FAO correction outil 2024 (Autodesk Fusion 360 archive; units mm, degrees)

design "FAO correction outil" references "brut correction outil", "Correction outil"
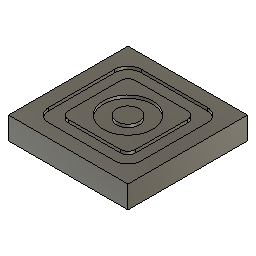
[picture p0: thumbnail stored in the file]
component_insert "Insertion d'un composant1"
component_insert "Insertion d'un composant2"
work_plane "Plan de construction" AlongDistance 0
sketch "Esquisse1" plane through (0, 0, 15) normal (0, 0, 1) x axis (1, 0, 0)
  line L1 (31, -22) -> (31, 22)
  line L2 (28.4, 4.5033) -> (25.5072, 1.0928)
  line L3 (28.4, -4.5033) -> (25.5072, -1.0928)
  line L4 (15.2762, -12.0803) -> (45.0436, 5.1058)
  line L5 (28.4, -4.5033) -> (26.4, -1.0392)
  arc A1 centre (25.8, 0) radius 5.2 clockwise from (28.4, 4.5033) to (28.4, -4.5033)
  circle C1 centre (25.5072, -1.0928) radius 4
  circle C2 centre (26.4, -1.0392) radius 4
  point P4 (31, 0)
  point P8 (25.5072, 1.0928)
  point P9 (25.5072, 1.0928)
  point P7 (28.4, 4.5033)
  point P10 (28.4, 4.5033)
  point P2 (25.5072, -1.0928)
  point P11 (25.5072, -1.0928)
  point P3 (28.4, -4.5033)
  point P12 (28.4, -4.5033)
  point P14 (25.5072, -1.0928)
  point P15 (26.4, -1.0392)
  point P18 (26.4, -1.0392)
  point P1 (0, 0)
  midpoint P4 L1
  coincident P8 P9
  coincident P7 P10
  coincident P2 P11
  coincident P3 P12
  coincident P4 A1
  tangent L1 A1
  coincident P2 P14
  tangent A1 C2
  coincident P12 C2
  tangent A1 L4
  coincident P12 L4
  coincident P15 P18
  dimension "d2" distance P1 P2 = 25.5072 (= "d3")
  dimension "d3" distance P1 P8 = 25.5072
  dimension "d4" distance P1 P2 = 1.0928
  dimension "d5" distance P1 P8 = 1.0928 (= "d4")
  dimension "d6" distance P1 P3 = 28.4
  dimension "d7" distance P1 P7 = 28.4 (= "d6")
  dimension "d8" distance P1 P7 = 4.5033
  dimension "d9" distance P1 P3 = 4.5033 (= "d8")
  dimension "d10" diameter C1 = 8
  dimension "d11" diameter C2 = 8
sketch "Esquisse2" plane through (0, 0, 15) normal (0, 0, 1) x axis (1, 0, 0)
  line L1 (31, -22) -> (31, 22)
  line L2 (28.6, 4.1569) -> (25.9072, 1.0928)
  line L3 (28.6, -4.1569) -> (25.9072, -1.0928)
  line L4 (33.5853, -1.2661) -> (26.6459, -5.29)
  line L5 (23.8353, 4.06) -> (28.6, -4.1569)
  arc A1 centre (26.2, 0) radius 4.8 clockwise from (28.6, 4.1569) to (28.6, -4.1569)
  circle C1 centre (26.5935, -0.6966) radius 4
  circle C2 centre (25.9072, -1.0928) radius 4
  circle C3 centre (26.3427, -0.264) radius 4
  point P2 (25.9072, 1.0928)
  point P3 (25.9072, -1.0928)
  point P4 (28.6, -4.1569)
  point P5 (28.6, 4.1569)
  point P6 (31, 0)
  point P10 (25.9072, 1.0928)
  point P11 (28.6, 4.1569)
  point P12 (25.9072, -1.0928)
  point P13 (28.6, -4.1569)
  point P14 (26.5935, -0.6966)
  point P18 (25.9072, -1.0928)
  point P19 (26.3427, -0.264)
  point P20 (26.3427, -0.264)
  point P1 (0, 0)
  vertical P2 P3
  vertical P4 P5
  midpoint P6 L1
  coincident P6 A1
  tangent L1 A1
  coincident P2 P10
  coincident P5 P11
  coincident P3 P12
  coincident P4 P13
  tangent A1 C1
  coincident P13 L4
  tangent A1 L4
  perpendicular L4 L5
  coincident P14 L5
  coincident P12 P18
  coincident L5 P19
  coincident P19 P20
  dimension "d12" distance P1 P2 = 25.9072
  dimension "d13" distance P1 P2 = 1.0928
  dimension "d14" distance P1 P3 = 1.0928 (= "d13")
  dimension "d15" distance P1 P5 = 28.6
  dimension "d16" distance P1 P5 = 4.1569
  dimension "d17" distance P1 P4 = 4.1569 (= "d16")
  dimension "d18" diameter C1 = 8
  dimension "d20" diameter C2 = 8
  dimension "d21" distance P14 P19 = 0.5
  dimension "d22" diameter C3 = 8
sketch "Esquisse3" plane through (0, 0, 15) normal (0, 0, 1) x axis (1, 0, 0)
  line L1 (31, -22) -> (31, 22)
  line L2 (30.5778, 2.3941) -> (26.5455, 1.7778)
  line L3 (30.5778, -2.3941) -> (26.5455, -1.7778)
  line L4 (33.1739, -4.7381) -> (28.8901, 7.0308)
  line L5 (25.6476, 0.5996) -> (32.956, 3.2598)
  arc A1 centre (24.0008, 0) radius 6.9992 clockwise from (30.5778, 2.3941) to (30.5778, -2.3941)
  circle C1 centre (26.5455, 1.7778) radius 4
  circle C2 centre (26.8191, 1.026) radius 4
  circle C3 centre (26.4432, 0.8892) radius 4
  point P3 (30.5778, 2.3941)
  point P4 (30.5778, -2.3941)
  point P2 (26.5455, 1.7778)
  point P9 (26.5455, 1.7778)
  point P10 (30.5778, 2.3941)
  point P5 (26.5455, -1.7778)
  point P11 (26.5455, -1.7778)
  point P12 (30.5778, -2.3941)
  point P13 (26.5455, 1.7778)
  point P18 (26.8191, 1.026)
  point P19 (26.4432, 0.8892)
  point P20 (26.4432, 0.8892)
  point P21 (26.0675, 0.7524)
  point P1 (0, 0)
  vertical P3 P4
  tangent L1 A1
  coincident P2 P9
  coincident P3 P10
  coincident P5 P11
  coincident P4 P12
  coincident P2 P13
  tangent A1 L4
  coincident P10 L4
  perpendicular L4 L5
  coincident P10 L5
  coincident L5 P18
  coincident P3 C2
  coincident L5 P19
  coincident P19 P20
  coincident L5 P21
  dimension "d23" distance P1 P2 = 26.5455
  dimension "d24" distance P1 P5 = 26.5455 (= "d23")
  dimension "d25" distance P1 P3 = 30.5778
  dimension "d26" distance P1 P3 = 2.3941
  dimension "d27" distance P1 P4 = 2.3941 (= "d26")
  dimension "d28" distance P1 P2 = 1.7778
  dimension "d29" distance P1 P5 = 1.7778 (= "d28")
  dimension "d30" diameter C1 = 8
  dimension "d31" diameter C2 = 8
  dimension "d32" distance P18 P19 = 0.4
  dimension "d33" diameter C3 = 8
  dimension "d34" distance P1 P21 = 0.7524
  dimension "d35" distance P1 P21 = 26.0675

design "brut correction outil"
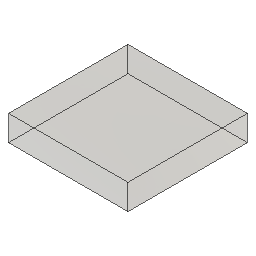
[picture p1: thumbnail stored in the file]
sketch "Esquisse" plane through (0, 0, 0) normal (0, 0, 1) x axis (1, 0, 0)
  line L1 (40, 40) -> (-40, 40)
  line L2 (40, -40) -> (40, 40)
  line L3 (-40, -40) -> (40, -40)
  line L4 (-40, 40) -> (-40, -40)
  line L5 (40, -40) -> (-40, 40)
  line L6 (-40, -40) -> (40, 40)
  point P6 (0, 0)
  point P1 (0, 0)
  point P4 (40, -40)
  point P5 (-40, -40)
  point P3 (40, 40)
  horizontal L1
  perpendicular L1 L2
  parallel L1 L3
  parallel L2 L4
  coincident L5 P6
  coincident L6 P6
  coincident P1 P6
  dimension "d1" distance P4 P5 = 80
  dimension "d2" distance P3 P4 = 80
extrude "Extrusion" new body sketch "Esquisse" profile of L1 L2 L3 L4 along normal blind 17

design "Correction outil"
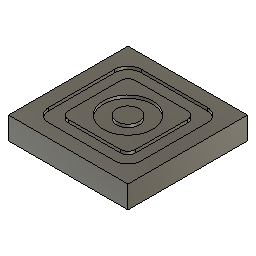
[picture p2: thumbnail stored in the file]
sketch "Esquisse1" plane through (0, 0, 0) normal (0, 0, 1) x axis (1, 0, 0)
  line L1 (-40, 40) -> (40, 40)
  line L2 (-40, -40) -> (-40, 40)
  line L3 (40, -40) -> (-40, -40)
  line L4 (40, 40) -> (40, -40)
  line L5 (-40, -40) -> (40, 40)
  line L6 (40, -40) -> (-40, 40)
  point P6 (0, 0)
  point P1 (0, 0)
  point P4 (-40, -40)
  point P5 (40, -40)
  point P3 (-40, 40)
  horizontal L1
  perpendicular L1 L2
  parallel L1 L3
  parallel L2 L4
  coincident L5 P6
  coincident L6 P6
  coincident P1 P6
  dimension "d1" distance P4 P5 = 80
  dimension "d2" distance P3 P4 = 80
extrude "Extrusion1" new body sketch "Esquisse1" profile of L1 L2 L3 L4 along normal blind 15
sketch "Esquisse2" plane through (0, 0, 15) normal (0, 0, 1) x axis (-1, 0, 0)
  line L1 (-31, 31) -> (31, 31)
  line L2 (-31, -31) -> (-31, 31)
  line L3 (31, -31) -> (-31, -31)
  line L4 (31, 31) -> (31, -31)
  line L5 (-31, -31) -> (31, 31)
  line L6 (31, -31) -> (-31, 31)
  line L7 (22.5, 22.5) -> (-22.5, 22.5)
  line L8 (22.5, -22.5) -> (22.5, 22.5)
  line L9 (-22.5, -22.5) -> (22.5, -22.5)
  line L10 (-22.5, 22.5) -> (-22.5, -22.5)
  line L11 (22.5, -22.5) -> (-22.5, 22.5)
  line L12 (-22.5, -22.5) -> (22.5, 22.5)
  point P6 (0, 0)
  point P1 (0, 0)
  point P11 (0, 0)
  point P7 (-22.5, 22.5)
  point P4 (-31, -31)
  point P5 (31, -31)
  point P3 (-31, 31)
  point P8 (22.5, 22.5)
  horizontal L1
  perpendicular L1 L2
  parallel L1 L3
  parallel L2 L4
  coincident L5 P6
  coincident L6 P6
  coincident P1 P6
  horizontal L7
  perpendicular L7 L8
  parallel L7 L9
  parallel L8 L10
  coincident L11 P11
  coincident L12 P11
  coincident L6 P7
  coincident P6 P11
  dimension "d5" distance P4 P5 = 62
  dimension "d6" distance P3 P4 = 62
  dimension "d7" distance P7 P8 = 45
extrude "Extrusion2" cut sketch "Esquisse2" profile of L1 L2 L3 L4 L7 L8 L9 L10 against normal blind 2
fillet "Congé1" radius 9
fillet "Congé2" radius 5
sketch "Esquisse3" plane through (0, 0, 15) normal (0, 0, 1) x axis (-1, 0, 0)
  circle C1 centre (0, 0) radius 7.5
  circle C2 centre (0, 0) radius 16.5
  point P1 (0, 0)
  point P2 (0, 0)
  coincident P1 P2
  concentric C1 C2
  dimension "d14" diameter C1 = 15
  dimension "d15" diameter C2 = 33
extrude "Extrusion3" cut sketch "Esquisse3" against normal blind 2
